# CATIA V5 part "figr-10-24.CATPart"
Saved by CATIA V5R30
Part number: Part1
Bounding box of the stored display mesh (mm): x -180.516 to 0, y -36.805 to 65.824, z 0 to 36.805
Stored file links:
  D:\PROJECTS\CATIA V56R 2020\Resources\Parts File\c10_catia_v5_6r2020_prt\figr-10-24.CATPart
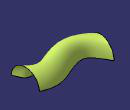
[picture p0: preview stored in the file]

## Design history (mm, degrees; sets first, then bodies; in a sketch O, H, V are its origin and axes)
Set1
  Sweep1: type Unspec, Profile Sketch2, Guide Sketch1
Body1 (main body)
  Sketch1 on xy-plane, origin (0, 0, 0), H (1, 0, 0), V (0, 1, 0)
    spline S1 through (0, 0) (-31.5913, 14.7273) (-94.8038, 0) (-174.5181, 29.5113)
    point P1 (0, 0)
    point P2 (-94.8038, 0)
    coincidence: P1 O, P2 H
  Sketch2 on yz-plane, origin (0, 0, 0), H (0, 1, 0), V (0, 0, 1)
    arc A1 centre (0, 0) radius 36.8048 from (36.8048, 0) to (-36.8048, 0) ccw
    point P1 (-36.8048, 0)
    point P2 (36.8048, 0)
    coincidence: P1 H, P2 H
